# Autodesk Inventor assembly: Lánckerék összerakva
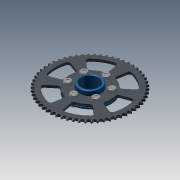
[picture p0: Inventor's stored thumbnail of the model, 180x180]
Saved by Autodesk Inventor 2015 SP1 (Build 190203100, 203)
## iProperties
Created: 2013-02
Part Number: Lánckerék összerakva
Document SubType Name: Assembly
Designer: Marci
Author: Marci
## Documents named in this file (5)
- C:\Users\TREINA11\Desktop\#01- Polymechanics and Automation\01 - 3D Models\Pneumatic System\Lánckerék összerakva.iam
- C:\Users\TREINA11\Desktop\#01- Polymechanics and Automation\01 - 3D Models\Pneumatic System\Lánckerékagy.ipt
- C:\Users\TREINA11\Desktop\#01- Polymechanics and Automation\01 - 3D Models\Pneumatic System\Roller Chain Sprocket11.ipt
- C:\Users\TREINA11\Desktop\#01- Polymechanics and Automation\01 - 3D Models\Pneumatic System\ISO 4017 - M8 x 16ISO.ipt
- C:\Users\TREINA11\Desktop\#01- Polymechanics and Automation\01 - 3D Models\Pneumatic System\ISO 4032 - M8ISO.ipt
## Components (14 placed, 4 different names)
1. Lánckerékagy:1 — Mate:1, Mate:2, Mate:3
2. Roller Chain Sprocket1:1 — Mate:1, Mate:2, Mate:3
3. ISO 4017 - M8 x 16ISO:1
4. ISO 4017 - M8 x 16ISO:2
5. ISO 4017 - M8 x 16ISO:3
6. ISO 4017 - M8 x 16ISO:4
7. ISO 4017 - M8 x 16ISO:5
8. ISO 4017 - M8 x 16ISO:6
9. ISO 4032 - M8ISO:1
10. ISO 4032 - M8ISO:2
11. ISO 4032 - M8ISO:3
12. ISO 4032 - M8ISO:4
13. ISO 4032 - M8ISO:5
14. ISO 4032 - M8ISO:6
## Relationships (3: Mate 3)
- Mate:1: Lánckerékagy:1 ↔ Roller Chain Sprocket1:1
- Mate:2: Lánckerékagy:1 ↔ Roller Chain Sprocket1:1
- Mate:3: Lánckerékagy:1 ↔ Roller Chain Sprocket1:1
